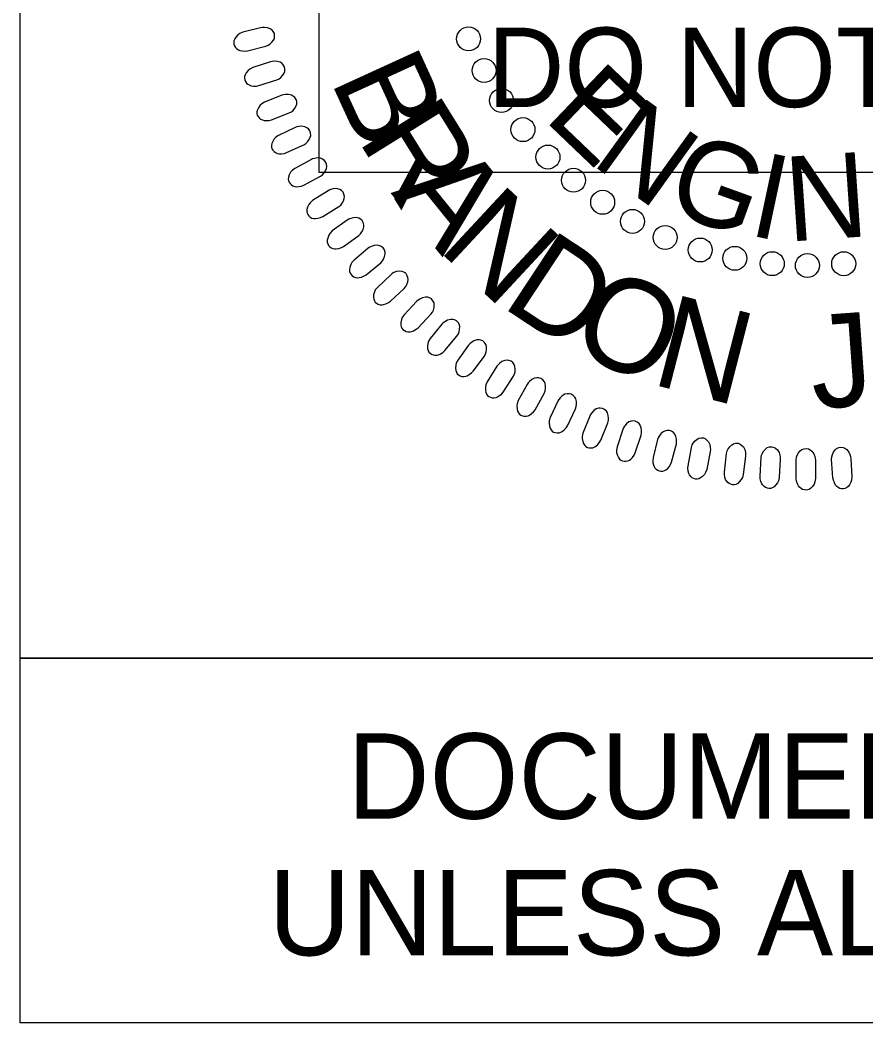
# Model space of a CAD drawing. Extents: x 18938 to 19565, y 6931 to 7973.
# Drawn here: x 19353.14 to 19360.49, y 7640.94 to 7649.66 of the extents above; entities that cross this region are included whole.
import ezdxf

# ---------------------------------------------------------------- set-up
doc = ezdxf.new("R2010")
doc.units = 0
for name, color, linetype in [('Old_Level_10', 7, 'Continuous'), ('Prop Pavement Schedule Description CELL', 7, 'Continuous'), ('Scratch_Level_5', 7, 'Continuous'), ('Typical Hinge Slope Interstate CELL', 7, 'Continuous'), ('Typical Pavement Slope Information CELL', 7, 'Continuous')]:
    doc.layers.add(name, color=color, linetype=linetype)

# ---------------------------------------------------------------- blocks, each defined once
blk = doc.blocks.new('Brandon J. McInnis')
at = {"layer": 'Old_Level_10'}
for points in [[(-87.757, 42.228), (-88.945, 41.923), (-89.148, 41.832), (-89.271, 41.747), (-89.407, 41.596), (-89.489, 41.475), (-89.538, 41.346), (-89.551, 41.235), (-89.542, 41.121), (-89.495, 41.018), (-89.437, 40.91), (-89.353, 40.823), (-89.23, 40.747), (-89.138, 40.708), (-88.976, 40.68), (-88.787, 40.667), (-88.628, 40.685), (-87.408, 40.989), (-87.249, 41.053), (-87.126, 41.132), (-86.993, 41.258), (-86.886, 41.401), (-86.833, 41.515), (-86.814, 41.682), (-86.832, 41.832), (-86.907, 41.967), (-86.982, 42.056), (-87.11, 42.155), (-87.304, 42.228), (-87.495, 42.249), (-87.627, 42.245)], [(-87.103, 39.944), (-88.269, 39.565), (-88.467, 39.462), (-88.584, 39.37), (-88.71, 39.21), (-88.785, 39.083), (-88.826, 38.952), (-88.831, 38.841), (-88.816, 38.728), (-88.762, 38.628), (-88.696, 38.523), (-88.608, 38.442), (-88.48, 38.374), (-88.386, 38.341), (-88.223, 38.323), (-88.034, 38.322), (-87.875, 38.349), (-86.677, 38.73), (-86.523, 38.804), (-86.404, 38.89), (-86.281, 39.024), (-86.182, 39.174), (-86.136, 39.291), (-86.128, 39.459), (-86.155, 39.607), (-86.239, 39.737), (-86.319, 39.821), (-86.452, 39.911), (-86.651, 39.973), (-86.842, 39.981), (-86.975, 39.969)], [(-86.344, 37.707), (-87.485, 37.256), (-87.675, 37.14), (-87.786, 37.04), (-87.902, 36.873), (-87.969, 36.742), (-88.001, 36.609), (-88, 36.497), (-87.978, 36.385), (-87.918, 36.289), (-87.846, 36.188), (-87.752, 36.113), (-87.62, 36.053), (-87.524, 36.026), (-87.36, 36.019), (-87.172, 36.029), (-87.015, 36.067), (-85.844, 36.522), (-85.694, 36.605), (-85.581, 36.698), (-85.466, 36.84), (-85.377, 36.996), (-85.338, 37.116), (-85.34, 37.284), (-85.377, 37.431), (-85.469, 37.554), (-85.554, 37.633), (-85.693, 37.715), (-85.895, 37.763), (-86.087, 37.76), (-86.218, 37.74)], [(-85.444, 35.547), (-86.555, 35.025), (-86.737, 34.898), (-86.842, 34.791), (-86.947, 34.617), (-87.005, 34.483), (-87.029, 34.347), (-87.021, 34.236), (-86.992, 34.126), (-86.926, 34.033), (-86.847, 33.937), (-86.749, 33.868), (-86.614, 33.816), (-86.517, 33.796), (-86.353, 33.798), (-86.164, 33.821), (-86.011, 33.868), (-84.87, 34.396), (-84.726, 34.489), (-84.619, 34.589), (-84.513, 34.737), (-84.434, 34.898), (-84.403, 35.021), (-84.416, 35.188), (-84.462, 35.332), (-84.561, 35.45), (-84.651, 35.524), (-84.795, 35.597), (-84.999, 35.632), (-85.191, 35.617), (-85.321, 35.589)], [(-84.397, 33.398), (-85.473, 32.808), (-85.646, 32.67), (-85.744, 32.556), (-85.839, 32.377), (-85.888, 32.238), (-85.904, 32.102), (-85.888, 31.991), (-85.852, 31.883), (-85.78, 31.795), (-85.696, 31.704), (-85.594, 31.641), (-85.456, 31.598), (-85.357, 31.583), (-85.194, 31.596), (-85.008, 31.631), (-84.857, 31.687), (-83.752, 32.286), (-83.614, 32.388), (-83.514, 32.494), (-83.417, 32.649), (-83.349, 32.815), (-83.325, 32.939), (-83.348, 33.105), (-83.403, 33.246), (-83.51, 33.357), (-83.604, 33.425), (-83.752, 33.488), (-83.959, 33.511), (-84.149, 33.484), (-84.276, 33.448)], [(-83.241, 31.324), (-84.277, 30.666), (-84.442, 30.518), (-84.532, 30.399), (-84.615, 30.213), (-84.656, 30.073), (-84.663, 29.935), (-84.641, 29.825), (-84.597, 29.72), (-84.52, 29.636), (-84.431, 29.551), (-84.325, 29.495), (-84.184, 29.46), (-84.085, 29.452), (-83.922, 29.475), (-83.739, 29.521), (-83.592, 29.587), (-82.527, 30.254), (-82.396, 30.363), (-82.302, 30.477), (-82.215, 30.638), (-82.157, 30.807), (-82.142, 30.932), (-82.176, 31.097), (-82.239, 31.234), (-82.353, 31.338), (-82.451, 31.4), (-82.603, 31.454), (-82.81, 31.464), (-82.999, 31.425), (-83.123, 31.38)], [(-81.964, 29.349), (-82.957, 28.628), (-83.112, 28.469), (-83.196, 28.345), (-83.266, 28.154), (-83.298, 28.011), (-83.296, 27.873), (-83.267, 27.766), (-83.218, 27.662), (-83.136, 27.584), (-83.041, 27.505), (-82.931, 27.455), (-82.789, 27.429), (-82.689, 27.428), (-82.529, 27.461), (-82.349, 27.518), (-82.206, 27.593), (-81.185, 28.326), (-81.061, 28.444), (-80.974, 28.562), (-80.898, 28.728), (-80.851, 28.901), (-80.843, 29.026), (-80.887, 29.189), (-80.959, 29.322), (-81.079, 29.419), (-81.181, 29.474), (-81.336, 29.519), (-81.543, 29.516), (-81.729, 29.465), (-81.851, 29.413)], [(-80.561, 27.467), (-81.506, 26.685), (-81.651, 26.517), (-81.726, 26.388), (-81.785, 26.194), (-81.808, 26.049), (-81.798, 25.912), (-81.762, 25.806), (-81.706, 25.706), (-81.619, 25.633), (-81.519, 25.56), (-81.407, 25.517), (-81.264, 25.5), (-81.164, 25.505), (-81.005, 25.548), (-80.829, 25.617), (-80.692, 25.7), (-79.718, 26.496), (-79.602, 26.621), (-79.524, 26.745), (-79.458, 26.915), (-79.421, 27.091), (-79.421, 27.216), (-79.475, 27.376), (-79.556, 27.504), (-79.681, 27.593), (-79.787, 27.642), (-79.945, 27.677), (-80.151, 27.661), (-80.333, 27.598), (-80.452, 27.539)], [(-79.051, 25.697), (-79.945, 24.857), (-80.08, 24.68), (-80.146, 24.547), (-80.193, 24.349), (-80.206, 24.203), (-80.188, 24.066), (-80.145, 23.962), (-80.083, 23.867), (-79.991, 23.799), (-79.887, 23.732), (-79.773, 23.697), (-79.628, 23.689), (-79.53, 23.7), (-79.374, 23.753), (-79.202, 23.832), (-79.07, 23.925), (-78.149, 24.78), (-78.041, 24.912), (-77.97, 25.041), (-77.914, 25.215), (-77.889, 25.392), (-77.898, 25.517), (-77.962, 25.674), (-78.05, 25.796), (-78.181, 25.877), (-78.289, 25.92), (-78.449, 25.944), (-78.654, 25.915), (-78.831, 25.841), (-78.946, 25.774)], [(-77.315, 23.919), (-78.155, 23.024), (-78.278, 22.839), (-78.336, 22.702), (-78.37, 22.501), (-78.375, 22.354), (-78.348, 22.22), (-78.299, 22.12), (-78.23, 22.028), (-78.135, 21.966), (-78.027, 21.906), (-77.91, 21.877), (-77.766, 21.879), (-77.668, 21.895), (-77.516, 21.958), (-77.35, 22.048), (-77.224, 22.149), (-76.358, 23.06), (-76.258, 23.199), (-76.195, 23.332), (-76.151, 23.509), (-76.138, 23.687), (-76.154, 23.812), (-76.227, 23.963), (-76.323, 24.081), (-76.459, 24.154), (-76.569, 24.189), (-76.73, 24.204), (-76.933, 24.161), (-77.106, 24.077), (-77.216, 24.003)], [(-75.625, 22.389), (-76.408, 21.443), (-76.519, 21.25), (-76.568, 21.11), (-76.589, 20.908), (-76.584, 20.761), (-76.549, 20.628), (-76.494, 20.53), (-76.42, 20.443), (-76.322, 20.388), (-76.21, 20.335), (-76.092, 20.314), (-75.947, 20.324), (-75.85, 20.347), (-75.703, 20.419), (-75.542, 20.519), (-75.423, 20.628), (-74.616, 21.592), (-74.525, 21.736), (-74.471, 21.873), (-74.438, 22.053), (-74.435, 22.231), (-74.459, 22.356), (-74.542, 22.501), (-74.645, 22.612), (-74.785, 22.676), (-74.898, 22.705), (-75.059, 22.709), (-75.259, 22.655), (-75.427, 22.559), (-75.531, 22.479)], [(-73.844, 20.988), (-74.566, 19.995), (-74.664, 19.796), (-74.704, 19.652), (-74.714, 19.449), (-74.699, 19.303), (-74.655, 19.173), (-74.594, 19.079), (-74.515, 18.997), (-74.413, 18.947), (-74.298, 18.901), (-74.179, 18.888), (-74.035, 18.907), (-73.94, 18.936), (-73.798, 19.018), (-73.644, 19.128), (-73.532, 19.244), (-72.787, 20.256), (-72.705, 20.406), (-72.66, 20.546), (-72.638, 20.727), (-72.646, 20.906), (-72.678, 21.027), (-72.77, 21.169), (-72.88, 21.273), (-73.024, 21.328), (-73.138, 21.349), (-73.299, 21.344), (-73.495, 21.276), (-73.656, 21.171), (-73.756, 21.083)], [(-71.942, 19.575), (-72.6, 18.539), (-72.687, 18.334), (-72.717, 18.188), (-72.714, 17.984), (-72.69, 17.84), (-72.638, 17.713), (-72.572, 17.622), (-72.487, 17.546), (-72.382, 17.502), (-72.265, 17.463), (-72.145, 17.458), (-72.003, 17.486), (-71.909, 17.522), (-71.773, 17.611), (-71.626, 17.731), (-71.521, 17.854), (-70.842, 18.91), (-70.77, 19.066), (-70.733, 19.208), (-70.723, 19.39), (-70.742, 19.568), (-70.782, 19.688), (-70.882, 19.823), (-70.998, 19.919), (-71.146, 19.966), (-71.261, 19.98), (-71.421, 19.964), (-71.613, 19.885), (-71.766, 19.769), (-71.861, 19.676)], [(-69.925, 18.359), (-70.516, 17.285), (-70.589, 17.074), (-70.611, 16.927), (-70.594, 16.724), (-70.562, 16.581), (-70.502, 16.457), (-70.43, 16.372), (-70.34, 16.3), (-70.233, 16.264), (-70.114, 16.232), (-69.994, 16.234), (-69.854, 16.271), (-69.763, 16.312), (-69.632, 16.411), (-69.493, 16.539), (-69.396, 16.668), (-68.784, 17.766), (-68.722, 17.925), (-68.694, 18.069), (-68.696, 18.252), (-68.726, 18.428), (-68.773, 18.545), (-68.882, 18.673), (-69.003, 18.763), (-69.153, 18.8), (-69.269, 18.807), (-69.429, 18.781), (-69.615, 18.689), (-69.761, 18.565), (-69.849, 18.466)], [(-67.865, 17.253), (-68.388, 16.143), (-68.447, 15.929), (-68.46, 15.78), (-68.431, 15.578), (-68.389, 15.438), (-68.322, 15.318), (-68.245, 15.237), (-68.151, 15.172), (-68.041, 15.142), (-67.921, 15.118), (-67.801, 15.128), (-67.663, 15.174), (-67.575, 15.22), (-67.45, 15.327), (-67.319, 15.463), (-67.231, 15.598), (-66.689, 16.732), (-66.637, 16.895), (-66.619, 17.04), (-66.631, 17.223), (-66.673, 17.397), (-66.728, 17.511), (-66.844, 17.632), (-66.971, 17.714), (-67.123, 17.741), (-67.239, 17.74), (-67.396, 17.705), (-67.576, 17.602), (-67.714, 17.468), (-67.796, 17.364)], [(-65.738, 16.245), (-66.19, 15.104), (-66.236, 14.886), (-66.239, 14.737), (-66.197, 14.538), (-66.147, 14.4), (-66.072, 14.285), (-65.99, 14.209), (-65.892, 14.149), (-65.782, 14.127), (-65.659, 14.111), (-65.54, 14.127), (-65.406, 14.182), (-65.321, 14.234), (-65.203, 14.348), (-65.081, 14.493), (-65.001, 14.633), (-64.532, 15.799), (-64.49, 15.964), (-64.481, 16.11), (-64.505, 16.292), (-64.557, 16.463), (-64.619, 16.573), (-64.742, 16.687), (-64.875, 16.76), (-65.028, 16.778), (-65.144, 16.77), (-65.298, 16.725), (-65.472, 16.611), (-65.601, 16.468), (-65.676, 16.359)], [(-63.529, 15.342), (-63.909, 14.176), (-63.941, 13.955), (-63.935, 13.807), (-63.88, 13.61), (-63.822, 13.476), (-63.739, 13.366), (-63.653, 13.296), (-63.552, 13.242), (-63.439, 13.226), (-63.316, 13.218), (-63.198, 13.242), (-63.068, 13.305), (-62.986, 13.362), (-62.876, 13.484), (-62.764, 13.636), (-62.693, 13.78), (-62.297, 14.973), (-62.266, 15.141), (-62.266, 15.288), (-62.302, 15.467), (-62.365, 15.635), (-62.433, 15.741), (-62.563, 15.846), (-62.7, 15.912), (-62.854, 15.92), (-62.969, 15.904), (-63.121, 15.849), (-63.286, 15.725), (-63.406, 15.575), (-63.475, 15.461)], [(-61.196, 14.669), (-61.502, 13.481), (-61.52, 13.26), (-61.505, 13.111), (-61.438, 12.919), (-61.371, 12.788), (-61.282, 12.684), (-61.191, 12.619), (-61.087, 12.572), (-60.974, 12.563), (-60.85, 12.563), (-60.734, 12.594), (-60.608, 12.665), (-60.53, 12.726), (-60.428, 12.855), (-60.325, 13.014), (-60.264, 13.163), (-59.943, 14.378), (-59.923, 14.548), (-59.932, 14.694), (-59.979, 14.871), (-60.053, 15.034), (-60.127, 15.136), (-60.265, 15.233), (-60.404, 15.289), (-60.559, 15.288), (-60.673, 15.266), (-60.821, 15.201), (-60.978, 15.066), (-61.089, 14.909), (-61.149, 14.791)], [(-57.674, 13.882), (-57.905, 12.677), (-57.982, 12.468), (-58.06, 12.341), (-58.202, 12.195), (-58.318, 12.106), (-58.443, 12.049), (-58.553, 12.029), (-58.667, 12.031), (-58.773, 12.071), (-58.885, 12.123), (-58.977, 12.201), (-59.061, 12.319), (-59.105, 12.409), (-59.143, 12.568), (-59.168, 12.756), (-59.16, 12.917), (-58.931, 14.152), (-58.877, 14.315), (-58.807, 14.443), (-58.689, 14.583), (-58.553, 14.699), (-58.442, 14.76), (-58.277, 14.789), (-58.126, 14.78), (-57.987, 14.713), (-57.894, 14.644), (-57.787, 14.523), (-57.702, 14.334), (-57.669, 14.144), (-57.665, 14.012)], [(-55.308, 13.556), (-55.463, 12.339), (-55.527, 12.126), (-55.596, 11.993), (-55.729, 11.839), (-55.839, 11.743), (-55.96, 11.677), (-56.069, 11.651), (-56.183, 11.646), (-56.291, 11.68), (-56.407, 11.724), (-56.503, 11.796), (-56.593, 11.909), (-56.643, 11.996), (-56.691, 12.153), (-56.728, 12.338), (-56.73, 12.499), (-56.58, 13.746), (-56.536, 13.912), (-56.474, 14.045), (-56.365, 14.192), (-56.237, 14.317), (-56.13, 14.383), (-55.967, 14.423), (-55.816, 14.424), (-55.673, 14.365), (-55.575, 14.303), (-55.461, 14.188), (-55.365, 14.005), (-55.32, 13.818), (-55.307, 13.686)], [(-52.991, 13.358), (-53.069, 12.134), (-53.119, 11.918), (-53.18, 11.781), (-53.303, 11.619), (-53.407, 11.515), (-53.524, 11.443), (-53.631, 11.409), (-53.745, 11.397), (-53.854, 11.425), (-53.972, 11.461), (-54.072, 11.527), (-54.171, 11.634), (-54.226, 11.717), (-54.283, 11.871), (-54.332, 12.054), (-54.344, 12.215), (-54.272, 13.469), (-54.239, 13.637), (-54.185, 13.773), (-54.086, 13.927), (-53.965, 14.059), (-53.863, 14.133), (-53.703, 14.182), (-53.552, 14.193), (-53.405, 14.143), (-53.305, 14.087), (-53.184, 13.98), (-53.075, 13.803), (-53.019, 13.619), (-52.998, 13.489)], [(-48.27, 13.409), (-48.194, 12.184), (-48.217, 11.963), (-48.26, 11.82), (-48.362, 11.644), (-48.452, 11.528), (-48.559, 11.442), (-48.661, 11.396), (-48.772, 11.369), (-48.884, 11.382), (-49.006, 11.404), (-49.114, 11.457), (-49.225, 11.551), (-49.29, 11.626), (-49.366, 11.772), (-49.437, 11.947), (-49.469, 12.105), (-49.556, 13.358), (-49.544, 13.529), (-49.507, 13.671), (-49.427, 13.836), (-49.325, 13.982), (-49.232, 14.068), (-49.08, 14.138), (-48.932, 14.167), (-48.78, 14.136), (-48.673, 14.093), (-48.539, 14.002), (-48.41, 13.84), (-48.331, 13.664), (-48.293, 13.537)], [(-50.637, 13.286), (-50.638, 12.059), (-50.676, 11.841), (-50.728, 11.7), (-50.84, 11.531), (-50.937, 11.421), (-51.05, 11.341), (-51.154, 11.302), (-51.266, 11.282), (-51.378, 11.302), (-51.498, 11.332), (-51.603, 11.391), (-51.707, 11.492), (-51.767, 11.571), (-51.834, 11.721), (-51.894, 11.9), (-51.916, 12.06), (-51.923, 13.316), (-51.901, 13.486), (-51.856, 13.626), (-51.766, 13.785), (-51.654, 13.925), (-51.556, 14.005), (-51.4, 14.064), (-51.25, 14.084), (-51.101, 14.044), (-50.996, 13.994), (-50.868, 13.895), (-50.75, 13.725), (-50.682, 13.545), (-50.653, 13.416)]]:
    blk.add_lwpolyline(points, close=True, dxfattribs=at)
for centre in [(-73.84, 41.476), (-72.805, 39.364), (-71.636, 37.36), (-70.203, 35.407), (-68.532, 33.574), (-66.82, 32.02), (-64.87, 30.546), (-62.88, 29.27), (-60.69, 28.194), (-58.342, 27.356), (-56.033, 26.798), (-53.525, 26.439), (-51.176, 26.318), (-48.747, 26.437)]:
    blk.add_circle(centre, 0.801, dxfattribs=at)
for s, height, rotation, p in [('B', 6.236, 294.5897, (-83.122, 38.747)), ('E', 5.669, 316.26559, (-68.882, 36.126)), ('R', 6.236, 301.86473, (-81.311, 34.79)), ('N', 5.669, 324.20538, (-65.747, 33.17)), ('G', 5.669, 340.08498, (-60.853, 30.072)), ('I', 5.669, 348.02477, (-55.225, 28.382)), ('N', 5.669, 3.90437, (-52.471, 27.91)), ('A', 6.236, 308.98157, (-79.069, 31.172)), ('N', 6.236, 317.09274, (-75.99, 27.424)), ('D', 6.236, 326.58243, (-71.76, 23.643)), ('O', 6.236, 335.45066, (-67.294, 20.785)), ('N', 6.236, 345.5505, (-61.742, 18.413)), ('J', 6.236, 4.1457, (-50.791, 16.721))]:
    blk.add_text(s, height=height, rotation=rotation, dxfattribs=at).set_placement(p)

msp = doc.modelspace()

# ---------------------------------------------------------------- linework, layer by layer
at = {"layer": 'Scratch_Level_5'}
msp.add_lwpolyline([(19355.7372, 7648.3313), (19355.7372, 7651.1513), (19373.3772, 7651.1513), (19373.3772, 7648.3313)], close=True, dxfattribs=at)
at = {"layer": 'Typical Hinge Slope Interstate CELL'}
for p, q in [((19353.1353, 7640.9362), (19353.1353, 7644.1089)), ((19353.1353, 7644.1089), (19380.142, 7644.1089)), ((19380.142, 7640.9362), (19353.1353, 7640.9362))]:
    msp.add_line(p, q, dxfattribs=at)
at = {"layer": 'Typical Pavement Slope Information CELL'}
msp.add_lwpolyline([(19353.1353, 7659.1534), (19366.642, 7659.1534), (19366.642, 7644.1089), (19353.1353, 7644.1089)], close=True, dxfattribs=at)

# ---------------------------------------------------------------- block references
at = {"layer": 'Prop Pavement Schedule Description CELL', "xscale": 0.13, "yscale": 0.13}
msp.add_blockref('Brandon J. McInnis', (19366.6353, 7644.1022), dxfattribs=at)

# ---------------------------------------------------------------- texts
at = {"layer": 'Scratch_Level_5'}
msp.add_text('DO NOT USE FOR R/W ACQUISITION', height=0.6912, dxfattribs=at).set_placement((19357.2012, 7648.9013))
at = {"layer": 'Typical Hinge Slope Interstate CELL'}
for s, p in [('DOCUMENT NOT CONSIDERED FINAL', (19355.98, 7642.7122)), ('UNLESS ALL SIGNATURES COMPLETED', (19355.2954, 7641.5241))]:
    msp.add_text(s, height=0.742545, dxfattribs=at).set_placement(p)

doc.saveas('drawing.dxf')
